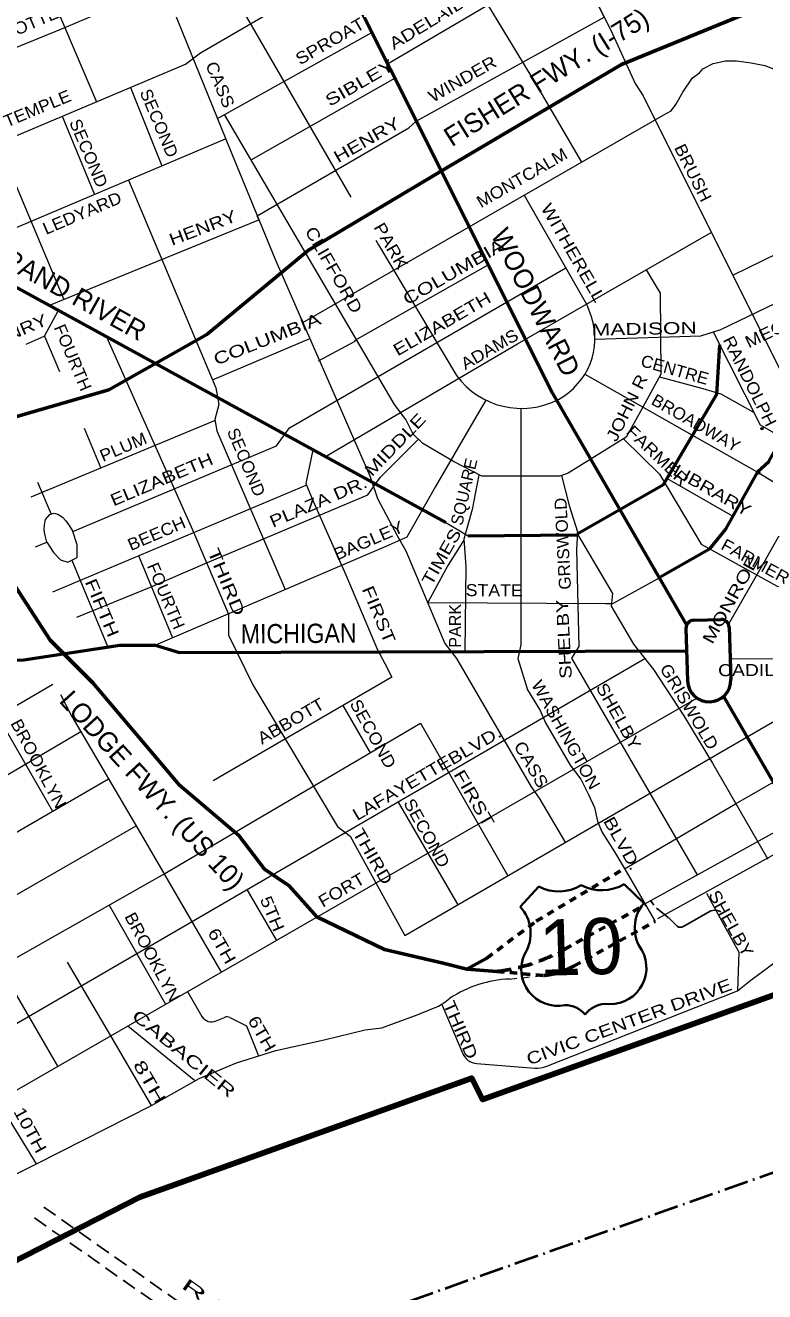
# Model space of a CAD drawing. Extents: x 34705 to 138605, y 34275 to 143551.
# Drawn here: x 95747 to 100351, y 96052 to 103945 of the extents above; entities that cross this region are included whole.
import ezdxf
from ezdxf.enums import TextEntityAlignment as Align

# ---------------------------------------------------------------- set-up
doc = ezdxf.new("R2010")
doc.units = 0
doc.header["$LTSCALE"] = 30
doc.header["$PDMODE"] = 32
doc.header["$PDSIZE"] = 15
for name, pattern in [('DOT_DASHED', [7.7, 5, -1.2, 0.3, -1.2]), ('MEDIUM_DASHED', [4.5, 3, -1.5]), ('SHORT_DASHED', [2.7, 1.5, -1.2])]:
    doc.linetypes.add(name, pattern=pattern)
for name, color, linetype, lineweight in [('1', 7, 'Continuous', 13), ('11', 7, 'Continuous', 13), ('51', 7, 'Continuous', 35), ('56', 7, 'DOT_DASHED', 40), ('58', 7, 'Continuous', 106), ('7', 7, 'MEDIUM_DASHED', 25)]:
    doc.layers.add(name, color=color, linetype=linetype, lineweight=lineweight)

msp = doc.modelspace()

# ---------------------------------------------------------------- linework, layer by layer
at = {"layer": '1'}
for p, q in [((98002.36, 103706.01), (99158.2, 104385.92)), ((96956.14, 104289.35), (97774.44, 102874.49)), ((96943.33, 103364.99), (97905.29, 103899.59)), ((96400.96, 103558.05), (96597.77, 103069.26)), ((97153.34, 103106.34), (98047.61, 103615.82)), ((99595.15, 103504.77), (100562.26, 101565.26)), ((95975.28, 103378.04), (96178.05, 102891.23)), ((97474.74, 102092.81), (99722.94, 103387.28)), ((95534.49, 102618.28), (96994.31, 103237.44)), ((98853.61, 102886.74), (99241.95, 102206.66)), ((100152.37, 102387.3), (100920.84, 102766.79)), ((97929.13, 102607.01), (97946.66, 102576.71)), ((97946.66, 102576.71), (98432.08, 101763.04)), ((95865.19, 102007.88), (95951.72, 102166.57)), ((99272.74, 102128.91), (99243.87, 102207.76)), ((95750.94, 101958.79), (95864.67, 102006.94)), ((95865.19, 102007.88), (95960.48, 101786.6)), ((96912.68, 101734.71), (97514.93, 101990.43)), ((100031.07, 102034.41), (100322.61, 101455.09)), ((99231.56, 101770.5), (100314.72, 101156.07)), ((96928.05, 101481.27), (95780.32, 101004.07)), ((96112.73, 101433.8), (96216.51, 101185.67)), ((100322.61, 101455.09), (100460.99, 101375.24)), ((99472.17, 101367.63), (99697.3, 101147.88)), ((97891.97, 101138.22), (97940.1, 100996.94)), ((99697.3, 101147.88), (99955.1, 100711)), ((99744.01, 101119.65), (100152.8, 100886.79)), ((95822.66, 101098.72), (95906.95, 100898.57)), ((95918.07, 100415.27), (97494.92, 101078.97)), ((98364.86, 100847.24), (98505.17, 100763.3)), ((99955.1, 100711), (100604, 100351.23)), ((96451.73, 100639.89), (96663.91, 100127.24)), ((96035.97, 100612.03), (96260.33, 100070.29)), ((96066.52, 100255.54), (96520.05, 100440.37)), ((98832.22, 100083.73), (98814.72, 99999.48)), ((93454.96, 96423.05), (99604.05, 99999.77)), ((99148.23, 100000.59), (99930.83, 98649.93)), ((100136.9, 99996.69), (100903.75, 100002.37)), ((98431.18, 99998.41), (98897.69, 99198.5)), ((98028.74, 99882.89), (96917.21, 99235.6)), ((97723.42, 99705.09), (97894.17, 99411.04)), ((98952.45, 99673.78), (98987.36, 99597.67)), ((98206.88, 99594.86), (98752.3, 98643.26)), ((98987.36, 99597.67), (99139.93, 99334.67)), ((98897.69, 99198.5), (98946.13, 99129.07)), ((98068.02, 99104.04), (98441.35, 98463.88)), ((98946.13, 99129.07), (99111.64, 98850.55)), ((97126.93, 98558.91), (97310.02, 98242.11)), ((96268.12, 98462.26), (96620.65, 97844.74)), ((100265.08, 97994.24), (100449.49, 98131.31)), ((100182.52, 97928.42), (100265.08, 97994.24)), ((96755.8, 97922.65), (96846.9, 97768.33)), ((98995.32, 97457.62), (100182.52, 97928.42)), ((98339.72, 97841.32), (98467.25, 97544.24)), ((96935.12, 97739.73), (96986.19, 97761.96)), ((97020.02, 97761.08), (97123.42, 97709.47)), ((96384.94, 97708.86), (96800.1, 97371.43)), ((97123.42, 97709.47), (97198.57, 97521.54)), ((98559.67, 97475.28), (98919.84, 97444.48))]:
    msp.add_line(p, q, dxfattribs=at)
at = {"layer": '1', "lineweight": 53}
for p, q in [((94695.3, 102855.98), (98364.86, 100847.24)), ((99184.41, 100776.03), (99722.16, 101082.45)), ((98505.17, 100763.3), (99182, 100768.8)), ((99705.27, 100510.5), (100006.82, 100682.33)), ((99909.66, 100237.41), (100079.04, 100242.24)), ((99861.11, 100186.01), (99870.44, 99858.92)), ((100130.44, 100193.88), (100140.98, 99867.67)), ((96706.96, 100036.41), (99865.08, 100046.85)), ((100096.67, 99760.57), (100568.5, 98942.91))]:
    msp.add_line(p, q, dxfattribs=at)
at = {"layer": '1', "linetype": 'SHORT_DASHED', "lineweight": 60}
for p, q in [((99106.3, 98187.89), (99610.9, 98465.99)), ((99164.49, 98082.32), (99669.09, 98360.42))]:
    msp.add_line(p, q, dxfattribs=at)
at = {"layer": '1', "lineweight": 25}
for p, q in [((99661.54, 98461.43), (99643.03, 98487.36)), ((99714.33, 98413.18), (99677.46, 98442.28)), ((99752.89, 98383.18), (99714.33, 98413.18))]:
    msp.add_line(p, q, dxfattribs=at)
at = {"layer": '1', "linetype": 'SHORT_DASHED'}
msp.add_line((98762.36, 98001.2), (98973.94, 98022.81), dxfattribs=at)
at = {"layer": '1'}
for points in [[(89474.59, 122846.01), (91544.38, 118695.87), (91485.34, 118525.26), (91445.98, 118334.96), (92122.6, 116967.52), (92180.3, 116877.74), (93371.26, 114453.63), (94086.27, 113029.71), (94119.06, 112950.97), (94335.54, 112517.89), (95799.33, 109586.03), (95857.03, 109444.94), (96036.54, 109117.87), (96762.63, 107683.46), (96913.51, 107335.68), (96965.99, 107178.2), (98202.49, 104747.04), (98412.4, 104425.51), (98930.62, 103572.47), (99211.35, 103092.72)], [(92402.65, 113894.18), (92751.37, 113182.28), (92816.97, 113064.17), (92902.24, 112946.05), (92967.84, 112775.44), (93151.51, 112329.24), (94584.81, 108982.71), (94643.84, 108818.66), (95260.46, 107342.24), (95601.56, 106522.01), (96598.64, 104210.61), (96644.56, 104099.06), (97018.46, 103180.4), (97300.53, 102491.4), (97891.97, 101138.22)], [(89620.31, 111530.82), (91301.99, 107601.17), (91366.1, 107415.19), (91673.83, 106703.33), (92808.58, 104033.88), (93975.39, 101263.41), (94552.01, 99871.59), (94676.64, 99628.81), (94945.59, 99182.6), (95948.05, 97457.03)], [(94005.91, 108658.63), (94158.42, 108254.34), (94820.96, 106686.06), (95214.54, 105754.27), (96190.89, 103469.22)], [(93695.7, 107547.6), (93857.2, 107315.71), (95985.91, 102236.51)], [(98127.48, 106458.82), (98314, 106085.66), (99403.93, 103891.18), (99544.97, 103583.35), (99595.15, 103504.77)], [(95144.29, 103549.28), (95370.73, 103656.57), (95446.38, 103708.96), (95987.58, 103930.16), (96605.73, 104193.38), (96625.21, 104146.06), (96936.12, 104314.36), (97524.26, 104662.79)], [(98181.84, 103346.84), (99351.96, 103995.82), (99302.9, 104094.6), (99608.67, 104250.66), (100118.87, 104480.34)], [(90738.5, 101138.28), (92958.63, 102086.3), (93540.56, 102319.15), (94588.03, 102755.74), (94861.54, 102907.09), (96744.08, 103703.14), (96837.19, 103772.99), (97713.93, 104285.09)], [(99722.94, 103387.28), (99769.27, 103412.36), (99798.86, 103450.75), (99842.7, 103527.53), (99902.98, 103618.58), (99944.63, 103649.29), (99966.55, 103673.42), (100031.21, 103707.42), (100106.84, 103723.88), (100175.89, 103723.88), (100267.96, 103710.71), (100353.44, 103695.36), (100427.97, 103664.65), (100516.75, 103592.25), (100561.79, 103491.9)], [(95893.81, 102198.34), (97201.84, 102732.45), (97191.46, 102757.81), (98136.25, 103305.36), (98181.84, 103346.84)], [(99614.31, 102421.5), (99699.79, 102275.32), (99704.67, 101771.24), (99580.03, 101541.58), (99488.19, 101377.53), (99127.41, 101154.43), (99074.93, 101134.74), (98589.51, 101134.74), (98412.4, 101226.61), (98222.17, 101338.16), (98163.13, 101397.22), (98117.21, 101489.08), (98045.05, 101580.95), (96987.71, 103389.65)], [(96388.91, 102980.67), (96933.19, 101685.94), (96952.87, 101580.95), (96926.63, 101489.08), (96939.75, 101416.9), (97364.27, 100428.13)], [(97616.29, 101257.01), (98812.85, 101959.69), (99237.66, 102204.18), (100018.96, 102654.84)], [(97573.34, 101854.91), (97800.29, 101977.16), (97800.29, 101982.98), (98628.55, 102452.89)], [(99294.82, 101989.53), (99953.93, 102009.11), (100078.46, 102049.95), (101044.67, 102514.4)], [(95810.07, 100694.42), (95880.64, 100724.25), (95921.91, 100658.78), (95965.04, 100614.21), (96010.85, 100599.46), (96070.15, 100629.12), (96070.15, 100706.97), (96042.63, 100790.78), (97311.47, 101325.18), (97392.94, 101435.79), (99112.94, 102432.59)], [(96251.78, 102003.95), (96788.87, 100800.09), (97011.9, 100275.14), (97011.9, 100143.9), (97162.78, 99835.5), (97690.83, 98951.29), (97769.55, 98892.23), (98110.29, 98272.91)], [(99695.71, 101754.74), (99967.05, 101681.02), (100078.57, 101648.21), (100282.44, 101534.92)], [(102120.41, 101810.31), (100563.19, 100890.26), (100492.44, 100854.88), (100344.23, 100593.4), (100126.07, 100212.76)], [(98614.32, 101609.06), (98537.03, 101477.6), (98300.88, 101070.77), (98123.77, 100755.8), (97992.58, 100696.74), (96556.49, 100082.78)], [(98832.22, 101555.3), (98832.22, 101346.37), (98832.22, 100083.73)], [(96520.05, 100440.37), (96880.84, 100597.54), (97880.66, 101017.77), (97957.41, 101127.27), (98196, 101365.93)], [(97537.48, 101300.16), (97494.57, 101089.17), (97539.96, 100978.9), (97743.31, 100519.57), (97940.1, 100053.68), (97986.02, 99968.38), (98028.74, 99882.89)], [(98571.29, 101144.19), (98530.47, 100926.41), (98478, 100742.68), (98491.12, 100572.07), (98484.33, 100042.37)], [(99085.72, 101138.79), (99133.97, 100952.66), (99186.45, 100788.61), (99179.89, 100677.06), (99193.01, 100073.37), (99148.23, 100000.59)], [(100314.72, 101156.07), (100432.79, 101083.89), (100708.3, 100565.51), (100852.62, 100263.66), (100875.57, 100199.69), (100901.81, 100015.96), (100975.12, 99876.03), (101224.39, 99442.95), (101264.44, 99339.2)], [(94980.43, 100951.02), (95187.4, 100460.27), (95427.18, 99889.61), (95483.49, 99796.13), (95916.43, 99048.07)], [(97940.1, 100996.94), (98064.73, 100760.72), (98117.21, 100668.85), (98359.92, 100091.41), (98431.18, 99998.41)], [(95880.64, 100724.25), (95868.7, 100772.87), (95864.44, 100802.73), (95866.14, 100831.73), (95872.11, 100865.85), (95900.25, 100896.56), (95925.82, 100904.23), (95949.7, 100897.41), (95977.83, 100880.35), (95998.3, 100856.46), (96020.46, 100828.32), (96042.63, 100790.78)], [(98478.45, 100736.74), (98378.82, 100579.37), (98254.2, 100347.23)], [(99185.59, 100774.02), (99402.92, 100403.1), (99396.36, 100324.36), (99534.11, 100088.14), (99658.75, 99930.65), (99848.98, 99641.93), (100026.09, 99346.65), (100371.83, 98747.71)], [(98110.29, 98272.91), (100009.04, 99376.15), (102090.6, 100583.48)], [(99478.07, 98688.78), (99802.13, 98877.38), (100168.74, 99092.76), (101094.01, 99622.49), (101739.95, 100006.69), (102742.33, 100585.9), (102800.43, 100626.14)], [(98254.2, 100347.23), (99359.86, 100341.41), (99406.42, 100341.41), (99706.59, 100508.22)], [(98814.72, 99999.48), (98873.46, 99804.05), (98952.45, 99673.78)], [(99605.2, 98470.47), (100537.56, 98984.31), (102441.56, 100068.5)], [(90341.13, 97271.2), (91097.91, 97592.35), (92040.63, 97982.37), (92114.36, 98006.08), (93683.61, 98661.67), (93789.34, 98705.66), (94435.28, 98973.43), (95918.22, 99838.32)], [(95965.96, 99773.77), (96034.5, 99641.93), (96480.57, 98880.75), (96965.97, 98043.79)], [(99685.37, 98378.76), (100623.55, 98895.81), (102197.18, 99791.88)], [(68439.64, 83130.91), (69240.62, 83379.94), (69351.18, 83443.98), (71166.8, 83996.99), (73724.39, 85148.13), (74227.76, 85392.62), (75135.57, 85904.88), (77195.6, 86958.51), (78743.53, 87721.08), (81322.94, 89059.96), (82067.81, 89449.98), (83313.14, 90160.16), (86113.68, 91749.34), (89963.15, 93974.49), (93143.39, 95827.08), (94534.21, 96642.05), (99929.58, 99752.11)], [(93898.5, 98265.83), (94592.4, 98670.73), (95476.93, 99182.99), (96092.18, 99543.48)], [(94102.64, 97206.72), (95593.32, 98079.88), (96600.06, 98650.35), (98206.88, 99594.86)], [(99139.93, 99334.67), (99206.13, 99246.57), (99252.04, 99154.71), (99291.4, 99069.4), (99311.08, 98984.1), (99337.32, 98918.48), (99416.04, 98793.81), (99501.31, 98649.44), (99669.09, 98360.42)], [(93492.55, 97684.04), (93632.22, 97748.07), (93677.3, 97751.12), (95511.85, 98813.35), (96265.19, 99248.27)], [(94130.13, 97620.96), (95378, 98347.65), (95529.31, 98434.97), (96436.14, 98956.57)], [(99989.09, 98536.78), (100189.48, 98168.46), (100182.52, 97928.42)], [(96008.27, 98106.46), (96277.2, 97646.77), (96530.57, 97211.89)], [(96828.47, 97381.34), (97061.48, 97479), (97307.32, 97555.29), (97607.66, 97621.16), (97862.3, 97683.56), (97967.53, 97697.02), (98186.13, 97778.53), (98319.7, 97832.4), (98359.04, 97856.57), (98390.93, 97881.74)], [(95216.66, 97857.76), (95529.41, 97338.72), (95627.8, 97154.99), (95815.09, 96848.98)], [(94973.04, 96430.02), (95820.27, 96851.61), (96531.68, 97212.52), (96828.47, 97381.34)]]:
    msp.add_lwpolyline(points, dxfattribs=at)
at = {"layer": '1', "lineweight": 53}
for points in [[(88660.55, 122435.75), (92843.2, 114028.76), (93335.18, 113024.79), (93440.14, 112782.01), (93902.59, 111904.36), (94112.5, 111523.77), (94525.77, 110657.61), (94939.03, 109837.38), (95188.3, 109345.24), (95267.02, 109133.63), (95601.56, 108418.39), (96001.71, 107709.71), (99029.01, 101651.49), (99866.2, 100204.4)], [(100306.08, 101161.35), (100378.24, 101226.23), (101046.16, 102428.97)], [(99722.16, 101082.45), (100052.8, 101645.39), (100071.67, 101953.74)], [(100306.08, 101161.35), (100107.48, 100805.59), (100006.82, 100682.33)], [(70273.25, 98655.39), (71057.35, 98936.8), (71901.7, 99280.47), (72734.73, 99461.12), (73549.47, 99618.3), (74194.43, 99751.98), (74462.66, 99868.63), (74760.14, 99892.09), (75412.24, 99851.32), (76511.78, 99857.14), (78835.21, 99868.78), (80080.52, 99857.14), (86770.24, 99915.34), (86956.45, 99956.09), (88909.68, 99973.56), (89759.8, 99996.86), (90394.28, 99932.82), (90847.72, 99926.99), (94474.35, 99938.64), (95736.38, 99991), (96334.87, 100081.57)], [(96334.87, 100081.57), (96556.49, 100082.78), (96706.96, 100036.41)]]:
    msp.add_lwpolyline(points, dxfattribs=at)
at = {"layer": '1', "linetype": 'SHORT_DASHED', "lineweight": 60}
msp.add_lwpolyline([(98620.56, 98130.4), (98928.29, 98361.64), (99478.07, 98688.78)], dxfattribs=at)
at = {"layer": '1', "lineweight": 25}
msp.add_lwpolyline([(100078.52, 98419.04), (100070.26, 98424.04), (100055.1, 98428.45), (100039.36, 98429.61), (100016.16, 98425.19), (99852.93, 98332.75), (99835.52, 98325.11), (99828.93, 98323.74), (99823.2, 98324.35), (99815.66, 98325.16), (99806.71, 98329.77), (99754.22, 98383.16)], dxfattribs=at)
at = {"layer": '1'}
for centre, radius, start, end in [((98836.17, 102057.04), 499.73, 216.03834, 297.50694), ((98796.46, 97258.04), 743.95, 92.62769, 123.03184), ((96907.18, 97803.91), 70, 210.5525, 293.52911), ((97002.16, 97725.29), 40, 63.47562, 113.52869), ((98566.19, 97580.43), 105.35, 200.09346, 266.451), ((98920.12, 97666.27), 221.79, 269.92695, 289.82107)]:
    msp.add_arc(centre, radius, start, end, dxfattribs=at)
at = {"layer": '1', "lineweight": 53}
for centre, start, end in [((99911.09, 100187.43), 91.63408, 181.63379), ((100080.46, 100192.26), 1.85164, 91.634)]:
    msp.add_arc(centre, 50, start, end, dxfattribs=at)
at = {"layer": '1', "linetype": 'MEDIUM_DASHED', "lineweight": 60}
for centre, radius, start, end in [((98552.3, 99155.18), 1114.7, 276.77208, 299.80159), ((98923.15, 98520.22), 500, 275.83051, 298.86002)]:
    msp.add_arc(centre, radius, start, end, dxfattribs=at)
at = {"layer": '1'}
msp.add_ellipse((98855.52, 101989.57), major_axis=(425.6, 111.28), ratio=0.978788, start_param=4.9639754, end_param=6.3512036, dxfattribs=at)
at = {"layer": '1', "lineweight": 53}
msp.add_ellipse((100005.71, 99863.3), major_axis=(135.27, 4.37), ratio=0.993321, start_param=3.1415927, end_param=6.2831853, dxfattribs=at)
at = {"layer": '1'}
for p in [(100334.4, 101431.67), (100314.72, 101156.07)]:
    msp.add_point(p, dxfattribs=at)
at = {"layer": '51'}
for p, q in [((99598.76, 98474.36), (99475.86, 98592.53)), ((98828.02, 98451.96), (98943.85, 98577.07))]:
    msp.add_line(p, q, dxfattribs=at)
at = {"layer": '51', "lineweight": 60}
msp.add_line((98496.05, 98062.81), (98620.56, 98130.4), dxfattribs=at)
at = {"layer": '51', "linetype": 'SHORT_DASHED', "lineweight": 60}
msp.add_line((98683.75, 98048.25), (98973.94, 98022.81), dxfattribs=at)
at = {"layer": '51', "lineweight": 60}
for points in [[(89237.66, 115479.85), (91499.64, 110952.67), (93420.76, 106565.37), (94042.42, 104827.01), (94275.43, 104074.61), (94754.53, 102737.63), (94761.52, 102513.8), (95607.58, 100567.59), (95901.26, 100112.95), (96166.96, 99847.16), (96705.36, 99210.66), (97075.95, 98895.9), (97236.78, 98686.07), (97390.6, 98581.15), (97562.53, 98387.67)], [(100708.3, 104431.99), (100301.7, 104046.37), (99460.75, 103701.33), (98388.89, 103068.27), (97510.88, 102543.58), (96878.03, 102018.88), (96266.56, 101672.41), (94157.06, 101062.17), (92788.73, 100605.91), (92053.25, 100332.16), (91322.06, 100332.16), (90426.94, 100400.6), (89697.17, 100337.86), (89332.28, 99932.93), (89286.67, 99488.08), (89309.48, 99071.74), (89383.59, 98792.29), (89913.82, 97593.19), (90193.19, 96937.32), (90347.13, 96349.89), (90369.93, 95910.74)], [(97562.53, 98387.67), (97984.57, 98185.89), (98348.52, 98099.93), (98496.05, 98062.81), (98683.75, 98048.25)]]:
    msp.add_lwpolyline(points, dxfattribs=at)
at = {"layer": '51'}
for centre, radius, start, end in [((99068.35, 98815.22), 268.73, 242.40256, 301.46889), ((99337.74, 98823.05), 268.73, 241.42362, 300.92744), ((98652.81, 98286.48), 241, 328.08598, 43.36339), ((99783.29, 98319.34), 241, 139.96661, 215.24402), ((99062.06, 98061.14), 226.89, 154.43005, 281.56253), ((99387.82, 98070.61), 226.89, 261.76747, 28.89995), ((99105.55, 97671.25), 167.61, 40.36594, 89.32063), ((99367.05, 97678.86), 167.61, 94.00937, 142.96406)]:
    msp.add_arc(centre, radius, start, end, dxfattribs=at)
at = {"layer": '56'}
msp.add_lwpolyline([(101333.7, 97121.46), (95399.61, 95024.99), (91130.54, 91667.28), (86478.26, 84854.43), (84052.84, 78374.69)], dxfattribs=at)
at = {"layer": '58'}
msp.add_lwpolyline([(109288.57, 102020.28), (107945.92, 101285.08), (107188.24, 100823.21), (106858.2, 100701.93), (106111.49, 100351.64), (105606.31, 100041.45), (105294.49, 99854.44), (104132.31, 99432.6), (103251.52, 99077.41), (102563.33, 98804.04), (102396.46, 98745.29), (102193.7, 98668.47), (101874.28, 98521.51), (101323.51, 98272.16), (101245.34, 98201.3), (98594.35, 97249.65), (98526.88, 97383.5), (96460.77, 96641.8), (94939.86, 95864.74)], dxfattribs=at)
at = {"layer": '7'}
for p, q in [((95860.98, 96580.19), (96831.69, 95897.79)), ((95803.68, 96512.38), (96777.2, 95828.01))]:
    msp.add_line(p, q, dxfattribs=at)

# ---------------------------------------------------------------- texts
at = {"layer": '11'}
for s, height, rotation, width, p in [('ADELAIDE', 75, 31.437, 1.25, (98306.17, 103951.75)), ('CHARLOTTE', 75, 23.07, 1.1, (95657.15, 103864.92)), ('SPROAT', 75, 30.043, 1.15, (97662.81, 103813.57)), ('CASS', 75, 292.933, 1.1, (96925.57, 103560.81)), ('SIBLEY', 75, 30.044, 1.35, (97847.29, 103554.98)), ('WINDER', 75, 29.842, 1.15, (98487.19, 103577.66)), ('TEMPLE', 75, 22.446, 1.1, (95835.53, 103392.11)), ('SECOND', 75, 292.931, 1.05, (96545.43, 103321.05)), ('SECOND', 75, 292.931, 1.05, (96106.54, 103133.78)), ('HENRY ', 75, 30.045, 1.3, (97907.81, 103208.05)), ('MONTCALM', 75, 30.044, 1.1, (98858.09, 102962.31)), ('BRUSH', 75, 296.44, 1.1, (99871.86, 103009.58)), ('LEDYARD', 75, 23.026, 1.1, (96115.14, 102740.41)), ('WITHERELL', 75, 299.88, 1.2, (99125.9, 102508.81)), ('HENRY ', 75, 20.83, 1.25, (96881.65, 102654.64)), ('CLIFFORD', 75, 299.88, 1.2, (97635.36, 102402.1)), ('PARK', 75, 299.88, 1.15, (97991.91, 102551.25)), ('COLUMBIA  ', 75, 30.044, 1.35, (98464.31, 102394.07)), ('ELIZABETH', 75, 30.126, 1.25, (98360.35, 102052.51)), ('MECHANIC', 75, 25.433, 1.15, (100529.73, 102063.56)), ('HENRY ', 75, 22.805, 1.25, (95705.75, 102002.04)), ('COLUMBIA  ', 75, 21.614, 1.35, (97300.77, 101968.61)), ('FOURTH', 75, 292.964, 1.05, (96008.08, 101859.89)), ('MADISON    ', 75, 1.092, 1.4, (99679.48, 102018.04)), ('ADAMS', 75, 30.127, 1.1, (98656.66, 101893.39)), ('RANDOLPH', 75, 296.443, 1.1, (100225.46, 101710.53)), ('CENTRE', 75, 344.105, 1.05, (99781.74, 101762.76)), ('JOHN R', 75, 63.829, 1.2, (99526.64, 101544.81)), ('BROADWAY', 75, 330.172, 1.05, (99904.77, 101434.16)), ('MIDDLE', 75, 46.143, 1.3, (98076.54, 101305.42)), ('SECOND', 75, 292.859, 1.05, (97088.42, 101208.01)), ('FARMER', 75, 316.316, 1.15, (99658.39, 101237.07)), ('PLUM', 75, 23.063, 1.1, (96371.09, 101282.57)), ('ELIZABETH', 75, 23.024, 1.25, (96610.07, 101079.71)), ('LIBRARY', 75, 330.172, 1.25, (100006.05, 101014.38)), ('PLAZA DR.', 75, 23.24, 1.25, (97586.11, 100940.76)), ('GRISWOLD', 75, 92.941, 1.05, (99131.03, 100716.3)), ('BEECH', 75, 23.237, 1.1, (96578.68, 100742.9)), ('BAGLEY', 75, 23.238, 1.15, (97899.51, 100699.85)), ('TIMES', 75, 60.443, 1.25, (98371.41, 100613.74)), ('FARMER', 75, 331.041, 1.1, (100276.06, 100571.06)), ('THIRD ', 75, 292.49, 1.45, (96971.91, 100443.51)), ('MONROE   ', 75, 61.033, 1.35, (100199.94, 100398.41)), ('FOURTH', 75, 292.964, 1.05, (96588.25, 100374.36)), ('FIFTH', 75, 292.86, 1.35, (96190.16, 100300.15)), ('FIRST', 75, 292.657, 1.3, (97913.64, 100258.3)), ('STATE', 75, 359.586, 1.1, (98666.97, 100386.54)), ('SHELBY ', 75, 92.941, 1.25, (99137.25, 100138.77)), ('MICHIGAN', 120, 0.448, 0.9, (97449.64, 100094.9)), ('GRISWOLD', 75, 300.955, 1.1, (99849.46, 99679.5)), ('CADILLAC SQ.', 75, 0.278, 1.2, (100476.07, 99890.22)), ('WASHINGTON', 75, 299.177, 1.1, (99080.6, 99505.55)), ('SHELBY', 75, 299.176, 1.15, (99408.85, 99620.83)), ('ABBOTT', 75, 30.353, 1.15, (97419.3, 99576.72)), ('SECOND', 75, 299.178, 1.1, (97879.45, 99511.22)), ('BROOKLYN', 75, 298.087, 1.1, (95796.18, 99325.33)), ('BLVD.', 75, 30.519, 1.25, (98563.61, 99423.77)), ('CASS', 75, 300.089, 1.15, (98864.84, 99319.55)), ('LAFAYETTE', 75, 30.516, 1.2, (98109.89, 99160.25)), ('FIRST', 75, 300.092, 1.35, (98509.29, 99108.67)), ('SECOND', 75, 299.178, 1.1, (98213.99, 98892.87)), ('BLVD.', 75, 299.18, 1.25, (99432.4, 98828.03)), ('THIRD', 75, 299.972, 1.25, (97877.91, 98746.74)), ('FORT', 75, 30.337, 1.15, (97734.92, 98523.98)), ('5TH', 75, 292.86, 1.2, (97250.45, 98393.23)), ('SHELBY', 75, 299.176, 1.15, (100109.16, 98329.51)), ('BROOKLYN', 75, 298.087, 1.1, (96506.14, 98120.64)), ('6TH', 75, 299.917, 1.25, (96938.68, 98188.49)), ('CIVIC CENTER DRIVE', 75, 20.466, 1.3, (99519.35, 97699.15)), ('THIRD', 75, 293.45, 1.25, (98423.11, 97669.49)), ('CABACIER    ', 75, 320.703, 1.55, (96777.06, 97452.96)), ('6TH', 75, 299.917, 1.25, (97188.33, 97641.65)), ('8TH       ', 75, 300.134, 1.55, (96565.31, 97210.07)), ('10TH', 75, 298.622, 1.25, (95744.03, 97041.56)), ('R.R.', 75, 324.893, 2.2, (96892.86, 95953.02))]:
    msp.add_text(s, height=height, rotation=rotation, dxfattribs=dict(at, width=width)).set_placement(p, align=Align.CENTER)
for s, height, rotation, p in [('FISHER FWY. (I-75)', 120, 31.894, (99023.1, 103570.89)), ('WOODWARD', 120, 297.076, (98871.69, 102191.94)), ('GRAND RIVER', 120, 330.982, (95969.2, 102244.85)), ('SQUARE', 75, 76.959, (98515.45, 101029.35)), ('PARK', 75, 90.149, (98460.29, 100202.54)), ('LODGE FWY. (US 10)', 120, 312.381, (96492.61, 99137.61))]:
    msp.add_text(s, height=height, rotation=rotation, dxfattribs=at).set_placement(p, align=Align.CENTER)
at = {"layer": '51'}
msp.add_text('10', height=350, rotation=1.665, dxfattribs=at).set_placement((99211.15, 98027.76), align=Align.CENTER)

doc.saveas('drawing.dxf')
